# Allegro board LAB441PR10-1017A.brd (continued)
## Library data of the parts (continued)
PQ101 QE9 = MMST3904-7-F_SOT323-3
PQ102 PQ103 = 2N7002KDWH_SOT363-6
PQ201 = CSD87312Q3E_SON8-4
PQ202 = DCX124EK-7-F_SC74R-6
PQ203 = SIR472DP-T1-GE3_POWERPAK8-5
PQ204 = SI4835DDY-T1-E3_SO8
PQ205 = SI7716ADN-T1-GE3_POWERPAK8-5
PQ206 PQ500 = DMN65D8LW-7_SOT323-3
PQ300 PQ301 = CSD87330Q3D_SON8-7
PQ409 QA1 QA3 QE12 QH6 QH7 = DMN66D0LDW-7_SOT363-6
PQ600 = MDV1528URH_PDFN33-8-5
PQ601 = MDV1526URH_PDFN33-8-5
PR107 PR309 PR310 PR402 PR407 R541 R1332 R1393 = R_0805
PR109 PR207 PR221 PR502 PR602 PR717 R1240 = R_1206
PR202 PR219 = R_1206_4P-D
PR211 PR222 PR307 PR308 PR503 PR600 PR603 PR714 PR715 PR721 R307 R531 R1242 RA84 RH350 RH405 RH407 RH408 = R_0603
PR732 R1321 R1322 R1326 R1329-R1331 R1342 R1344 R2669 RH340 = R0805_0OHM
PRP100 RP2 RP4-RP8 RP14-RP16 RP20 RP21 RPE5 RPE7 = RP_0804_8P4R
PU200 = BQ24777RUYR_WQFN28_4X4
PU300 = TPS51285BRUKR_QFN20_3X3
PU400 PU401 = TLV62150RGTR_QFN16_3X3
PU404 = LM393DMR2G_MICRO8
PU405 PU406 = M74VHC1GT00DFT2G_SC70-5
PU500 = SY8206DQNC_QFN10_3X3
PU600 = G5616ARZ1U_TQFN20_3X3
PU700 = TPS51624RSM_QFN32_4X4
PU701 = CSD97374CQ4M_SON8_3P5X4P5
Q39 Q40 Q71 Q305 Q362 QA6 QA8 QA9 QC5 = SSM3K7002FU_SC70-3
Q70 = AO4407AL_SO8
Q360 = SIS412DN-T1-GE3_POWERPAK8-5
Q361 = SI1553CDL-T1-GE3_SC70-6
QA7 QV2 = LBSS138LT1G_SOT23-3
QE3 QE4 QE8 QE10 QE11 = MMBT3904WT1G_SC70-3
R309 R1125 R1318 R1320 R1323 R1343 R2670 R2671 RA80 RA83 RH341 RH348 RH354-RH357 RH3527 = R0603_0OHM
RP13 = RP_1206_10P8R
SW2 = SW_SKRBAAE010_4P
SW3 = SW_NTC311-EA1T-A160T_4P
SW4 = SW_SSAL120100_3P
T2 T123-T125 T226-T231 T263-T269 T273 T275-T279 T281 T282 T284 T286-T293 = TPC12
U34 = APE8937GN2_DFN8_2X2
U48 = W25Q64FVSSIQ_SO8
U652 = AT97SC3205_TSSOP28
U663 = 74CBTLV3126DS_SSOP16
U664 U715-U720 = TPS22966DPUR_SON14_2X3
U671 = TXB0104PWR_TSSOP14
U672 UC1 = 74AUP1G07GW_TSSOP5
U673 = NCP4545IMNTWG_QFN18_3X3
U675 U697 UH5 = MC74VHC1G08DFT2G_SC70-5
U679 = NLSX0102FCT1G_FLIP-CHIP8
U682 U683 = NL17SZ14DFT2G_SOT353-5
U699 = MC74VHC1G32DFT2G_SC70-5
U708 = SN74AUP1G04DCKR_SC70-5
U726 = AP2337SA-7_SOT23-3
U727 = W25Q32FVSSIQ_SO8
U728 = G9091-330TO1U_TSOT-23-5
UA2 = ALC3263-CG_QFN56_7X7
UC6 = TC7SH08FU_SSOP5
UCPU1 = SHARK-BAY-ULT_BGA_1168P-T
UD1 UD3 UD4 UD7 UD28 UD29 UD31 UD32 = MT41J256M16RE-15E-D_FBGA_96P
UE4 = MCP23017T-E-ML_QFN28_6X6
UE5 = MEC5085-LZY_DQFN132_11X11
US2 = G547I1P81U_MSOP8
UV1 = SN74CBT3257CPWR_TSSOP16
YE1 = Y_Q13FC135000040_2P
YH1 = Y_CM31532768DZFT_2P
YH2 = Y_X3G024000DC1H_4P

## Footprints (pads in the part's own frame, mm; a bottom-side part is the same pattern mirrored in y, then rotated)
2N7002KDWH_SOT363-6
  oval 0.356x0.889 smd: 1(0,0) 2(0.65,0) 3(1.3,0) 4(1.3,1.6) 5(0.65,1.6) 6(0,1.6)
74AUP1G07GW_TSSOP5
  oval 0.381x1.346 smd: 1(0,0) 2(0.65,0) 3(1.3,0) 4(1.3,1.79) 5(0,1.79)
74CBTLV3126DS_SSOP16
  oval 0.381x1.676 smd: 1(0,0) 2(0.635,0) 3(1.27,0) 4(1.905,0) 5(2.54,0) 6(3.175,0) 7(3.81,0) 8(4.445,0) 9(4.445,5.35) 10(3.81,5.35) 11(3.175,5.35) 12(2.54,5.35) 13(1.905,5.35) 14(1.27,5.35) 15(0.635,5.35) 16(0,5.35)
ACES_50224-00401-001_4P
  oval 0.61x1.549 smd: 1(0,0) 2(1,0) 3(2,0) 4(3,0)
  rect 1.194x1.803 smd: 5(4.3,-3.875) 6(-1.3,-3.875)
ACES_50278-00201-001_2P
  oval 0.787x1.905 smd: 1(0,0) 2(1.25,0)
  rect 1.295x3.353 smd: 3(-2.85,-4.925) 4(4.1,-4.925)
ACES_50398-04041-001_40P
  oval 0.254x1.295 smd: 1(0,0) 2(0.5,0) 3(1,0) 4(1.5,0) 5(2,0) 6(2.5,0) 7(3,0) 8(3.5,0) 9(4,0) 10(4.5,0) 11(5,0) 12(5.5,0) 13(6,0) 14(6.5,0) 15(7,0) 16(7.5,0) 17(8,0) 18(8.5,0) 19(9,0) 20(9.5,0) 21(10,0) 22(10.5,0) 23(11,0) 24(11.5,0) 25(12,0) 26(12.5,0) 27(13,0) 28(13.5,0) 29(14,0) 30(14.5,0) 31(15,0) 32(15.5,0) 33(16,0) 34(16.5,0) 35(17,0) 36(17.5,0) 37(18,0) 38(18.5,0) 39(19,0) 40(19.5,0)
  rect 1.194x3.2 smd: 41(-2.4,1.95) 45(21.9,1.95)
  rect 2.311x1.295 smd: 42(0.85,3.9) 43(9.75,3.9) 44(18.65,3.9)
ACES_50506-01841-P01_18P
  oval 0.305x0.889 smd: 1(0,0) 2(0.5,0) 3(1,0) 4(1.5,0) 5(2,0) 6(2.5,0) 7(3,0) 8(3.5,0) 9(4,0) 10(4.5,0) 11(5,0) 12(5.5,0) 13(6,0) 14(6.5,0) 15(7,0) 16(7.5,0) 17(8,0) 18(8.5,0)
  rect 0.991x2.007 smd: 19(-2.1,-3.05) 20(10.6,-3.05)
ACES_88266-05001_5P
  oval 0.787x2.007 smd: 1(0,0) 2(1.25,0) 3(2.5,0) 4(3.75,0) 5(5,0)
  rect 2.007x2.489 smd: 6(7.2,-4.05) 7(-2.2,-4.05)
ALC3263-CG_QFN56_7X7
  oval 0.203x0.889 smd: 1(0,0) 2(0.4,0) 3(0.8,0) 4(1.2,0) 5(1.6,0) 6(2,0) 7(2.4,0) 8(2.8,0) 9(3.2,0) 10(3.6,0) 11(4,0) 12(4.4,0) 13(4.8,0) 14(5.2,0) 29(5.2,7.1) 30(4.8,7.1) 31(4.4,7.1) 32(4,7.1) 33(3.6,7.1) 34(3.2,7.1) 35(2.8,7.1) 36(2.4,7.1) 37(2,7.1) 38(1.6,7.1) 39(1.2,7.1) 40(0.8,7.1) 41(0.4,7.1) 42(0,7.1)
  oval 0.889x0.203 smd: 15(6.15,0.95) 16(6.15,1.35) 17(6.15,1.75) 18(6.15,2.15) 19(6.15,2.55) 20(6.15,2.95) 21(6.15,3.35) 22(6.15,3.75) 23(6.15,4.15) 24(6.15,4.55) 25(6.15,4.95) 26(6.15,5.35) 27(6.15,5.75) 28(6.15,6.15) 43(-0.95,6.15) 44(-0.95,5.75) 45(-0.95,5.35) 46(-0.95,4.95) 47(-0.95,4.55) 48(-0.95,4.15) 49(-0.95,3.75) 50(-0.95,3.35) 51(-0.95,2.95) 52(-0.95,2.55) 53(-0.95,2.15) 54(-0.95,1.75) 55(-0.95,1.35) 56(-0.95,0.95)
  rect 4.597x4.597 smd: 57(2.6,3.55)
AO4407AL_SO8
  oval 0.635x1.854 smd: 1(0,0) 2(1.27,0) 3(2.54,0) 4(3.81,0) 5(3.81,5.165) 6(2.54,5.165) 7(1.27,5.165) 8(0,5.165)
AP2337SA-7_SOT23-3
  oval 1.016x1.524 smd: 1(0,0) 2(0.965,2.083) 3(-0.965,2.083)
APE8937GN2_DFN8_2X2
  oval 0.254x0.787 smd: 1(0,0) 2(0.5,0) 3(1,0) 4(1.5,0) 5(1.5,2.2) 6(1,2.2) 7(0.5,2.2) 8(0,2.2)
  rect 1.6x0.889 smd: 9(0.75,1.1)
AT97SC3205_TSSOP28
  oval 0.381x1.626 smd: 1(0,0) 2(0.65,0) 3(1.3,0) 4(1.95,0) 5(2.6,0) 6(3.25,0) 7(3.9,0) 8(4.55,0) 9(5.2,0) 10(5.85,0) 11(6.5,0) 12(7.15,0) 13(7.8,0) 14(8.45,0) 15(8.45,5.8) 16(7.8,5.8) 17(7.15,5.8) 18(6.5,5.8) 19(5.85,5.8) 20(5.2,5.8) 21(4.55,5.8) 22(3.9,5.8) 23(3.25,5.8) 24(2.6,5.8) 25(1.95,5.8) 26(1.3,5.8) 27(0.65,5.8) 28(0,5.8)
AZ5125-01HPR7G_SOD523-2
  rect 0.61x0.787 smd: 1(0,0) 2(1.5,0)
AZ5125-02SPR7G_SOT23-3
  oval 1.016x1.524 smd: 1(0,0) 2(0.965,2.083) 3(-0.965,2.083)
BAS40-04_SOT23-3
  oval 1.016x1.524 smd: 1(0,0) 2(0.965,2.083) 3(-0.965,2.083)
BAT54A-7-F_SOT23-3
  oval 1.016x1.524 smd: 1(0,0) 2(0.965,2.083) 3(-0.965,2.083)
BAT54CW-7-F_SOT323-3
  oval 0.711x0.889 smd: 1(0,0) 2(-0.65,-1.9) 3(0.65,-1.9)
BQ24777RUYR_WQFN28_4X4
  oval 0.889x0.203 smd: 1(0,0) 2(0,-0.4) 3(0,-0.8) 4(0,-1.2) 5(0,-1.6) 6(0,-2) 7(0,-2.4) 15(4.1,-2.4) 16(4.1,-2) 17(4.1,-1.6) 18(4.1,-1.2) 19(4.1,-0.8) 20(4.1,-0.4) 21(4.1,0)
  oval 0.203x0.889 smd: 8(0.85,-3.25) 9(1.25,-3.25) 10(1.65,-3.25) 11(2.05,-3.25) 12(2.45,-3.25) 13(2.85,-3.25) 14(3.25,-3.25) 22(3.25,0.85) 23(2.85,0.85) 24(2.45,0.85) 25(2.05,0.85) 26(1.65,0.85) 27(1.25,0.85) 28(0.85,0.85)
  rect 2.591x2.591 smd: 29(2.05,-1.2)
C_0402
  rect 0.508x0.559 smd: 1(0,0) 2(0.914,0)
C_0603
  rect 0.635x0.889 smd: 1(0,0) 2(1.397,0)
C_0805
  rect 0.813x1.397 smd: 1(0,0) 2(1.702,0)
C_1210
  oval 1.27x2.794 smd: 1(0,0) 2(3.048,0)
C_A1
  rect 1.346x1.499 smd: 1(0,0) 2(2.45,0)
C_B
  rect 1.549x2.464 smd: 1(0,0) 2(3.378,0)
C_B2
  rect 1.346x2.692 smd: 1(0,0) 2(-2.75,0)
C_D2
  rect 2.388x2.794 smd: 1(0,0) 2(6.4,0)
CHILI_PBY100505T-600Y-N_2P
  rect 0.457x0.508 smd: 1(0,0) 2(0.85,0)
CONCR_213EBAA2FKA_67P
  round 1.092 hole 1.092 unplated: (-0.75,-5.275)
  round 1.6 hole 1.6 unplated: (19.25,-5.275)
  oval 0.305x1.549 smd: 1(0,0) 2(0.25,-7.55) 3(0.5,0) 4(0.75,-7.55) 5(1,0) 6(1.25,-7.55) 7(1.5,0) 8(1.75,-7.55) 9(2,0) 10(2.25,-7.55) 11(2.5,0) 12(2.75,-7.55) 13(3,0) 14(3.25,-7.55) 15(3.5,0) 16(3.75,-7.55) 17(4,0) 18(4.25,-7.55) 19(4.5,0) 20(4.75,-7.55) 21(5,0) 22(5.25,-7.55) 23(5.5,0) 24(7.75,-7.55) 25(8,0) 26(8.25,-7.55) 27(8.5,0) 28(8.75,-7.55) 29(9,0) 30(9.25,-7.55) 31(9.5,0) 32(9.75,-7.55) 33(10,0) 34(10.25,-7.55) 35(10.5,0) 36(10.75,-7.55) 37(11,0) 38(11.25,-7.55) 39(11.5,0) 40(11.75,-7.55) 41(12,0) 42(12.25,-7.55) 43(12.5,0) 44(12.75,-7.55) 45(13,0) 46(13.25,-7.55) 47(13.5,0) 48(13.75,-7.55) 49(14,0) 50(14.25,-7.55) 51(14.5,0) 52(14.75,-7.55) 53(15,0) 54(15.25,-7.55) 55(15.5,0) 56(15.75,-7.55) 57(16,0) 58(16.25,-7.55) 59(16.5,0) 60(16.75,-7.55) 61(17,0) 62(17.25,-7.55) 63(17.5,0) 64(17.75,-7.55) 65(18,0) 66(18.25,-7.55) 67(18.5,0)
  rect 1.194x2.743 smd: 68(-1.1,-0.775) 69(19.6,-0.775)
CONCR_213MAAA32FA_67P-T
  round 1.092 hole 1.092 unplated: (-0.75,-5.275)
  round 1.6 hole 1.6 unplated: (19.25,-5.275)
  oval 0.305x1.549 smd: 1(0,0) 2(0.25,-7.55) 3(0.5,0) 4(0.75,-7.55) 5(1,0) 6(1.25,-7.55) 7(1.5,0) 8(1.75,-7.55) 9(2,0) 10(2.25,-7.55) 11(2.5,0) 12(2.75,-7.55) 13(3,0) 14(3.25,-7.55) 15(3.5,0) 16(3.75,-7.55) 17(4,0) 18(4.25,-7.55) 19(4.5,0) 20(4.75,-7.55) 21(5,0) 22(5.25,-7.55) 23(5.5,0) 24(5.75,-7.55) 25(6,0) 26(6.25,-7.55) 27(6.5,0) 28(6.75,-7.55) 29(7,0) 30(7.25,-7.55) 31(7.5,0) 32(7.75,-7.55) 33(8,0) 34(8.25,-7.55) 35(8.5,0) 36(8.75,-7.55) 37(9,0) 38(9.25,-7.55) 39(9.5,0) 40(9.75,-7.55) 41(10,0) 42(10.25,-7.55) 43(10.5,0) 44(10.75,-7.55) 45(11,0) 46(11.25,-7.55) 47(11.5,0) 48(11.75,-7.55) 49(12,0) 50(12.25,-7.55) 51(12.5,0) 52(12.75,-7.55) 53(13,0) 54(13.25,-7.55) 55(13.5,0) 56(13.75,-7.55) 57(14,0) 58(14.25,-7.55) 59(16.5,0) 60(16.75,-7.55) 61(17,0) 62(17.25,-7.55) 63(17.5,0) 64(17.75,-7.55) 65(18,0) 66(18.25,-7.55) 67(18.5,0)
  rect 1.194x2.743 smd: 68(-1.1,-0.775) 69(19.6,-0.775)
CSD87312Q3E_SON8-4
  rect 2.388x0.66 smd: 1(0,0)
  rect 0.432x0.66 smd: 2(0.975,2.95)
  rect 1.753x0.66 smd: 3(-0.325,2.95)
  custom 0.475x0.475 smd: 4(0,1.475)
CSD87330Q3D_SON8-7
  oval 1.092x0.66 smd: 1(0,0)
  oval 0.432x0.66 smd: 2(0.975,0) 3(1.625,0) 4(1.625,2.95) 5(0.975,2.95) 6(0.325,2.95) 7(-0.325,2.95)
  custom 0.475x0.475 smd: 8(0.65,1.475)
CSD97374CQ4M_SON8_3P5X4P5
  oval 0.203x0.889 smd: 1(0,0) 2(0.4,0) 3(0.8,0) 6(0.8,3.5) 7(0.4,3.5) 8(0,3.5)
  custom 0.225x0.225 smd: 4(2.2,0.262) 5(2.2,3.238)
  rect 4.039x2.21 smd: 9(1.6,1.75)
CVILU_CI1806M2HRP-NH_6P
  oval 0.508x0.991 smd: 1(0,0) 2(0.8,0) 3(1.6,0) 4(2.4,0) 5(3.2,0) 6(4,0)
  rect 1.194x1.702 smd: 7(5.3,-1.95) 8(-1.3,-1.95)
DCX124EK-7-F_SC74R-6
  oval 0.559x0.787 smd: 1(0,0) 2(-0.95,0) 3(-1.9,0) 4(-1.9,2.4) 5(-0.95,2.4) 6(0,2.4)
DMN65D8LW-7_SOT323-3
  oval 0.711x0.889 smd: 1(0,0) 2(-0.65,-1.9) 3(0.65,-1.9)
DMN66D0LDW-7_SOT363-6
  oval 0.432x0.61 smd: 1(0,0) 2(0.65,0) 3(1.3,0) 4(1.3,1.9) 5(0.65,1.9) 6(0,1.9)
E-T_6705K-Y08N-40L_8P
  oval 0.305x1.092 smd: 1(0,0) 2(0.5,0) 3(1,0) 4(1.5,0) 5(2,0) 6(2.5,0) 7(3,0) 8(3.5,0)
  rect 0.991x2.007 smd: 9(-2.1,-3.15) 10(5.6,-3.15)
E-T_6705K-Y15N-00L_15P
  oval 0.305x0.889 smd: 1(0,0) 2(0.5,0) 3(1,0) 4(1.5,0) 5(2,0) 6(2.5,0) 7(3,0) 8(3.5,0) 9(4,0) 10(4.5,0) 11(5,0) 12(5.5,0) 13(6,0) 14(6.5,0) 15(7,0)
  rect 0.991x2.007 smd: 16(-2.1,-3.05) 17(9.1,-3.05)
E-T_6710K-Y15M-31L_15P
  oval 0.305x0.965 smd: 1(0,0) 2(0.5,0) 3(1,0) 4(1.5,0) 5(2,0) 6(2.5,0) 7(3,0) 8(3.5,0) 9(4,0) 10(4.5,0) 11(5,0) 12(5.5,0) 13(6,0) 14(6.5,0) 15(7,0)
  rect 0.305x1.143 smd: 16(7.885,-2.965) 17(-0.885,-2.965)
EMIST_SUL-12A2M_1P
  rect 6.909x1.194 smd: 1(0,0)
ESD207-B1-02EL_TSLP-2-19-2
  rect 0.356x0.61 smd: 1(0,0) 2(0.65,0)
FDV301N_NL_SOT23-3
  oval 1.016x1.524 smd: 1(0,0) 2(0.965,2.083) 3(-0.965,2.083)
FIDUCIAL_C40M80
  round 1.016 smd: 1(0,0)
FOX_GS73091-10272-7H_9P-T
  rect 0.66x5.004 smd: 1(0,0) 2(-1.5,0) 3(-3,0) 4(-4.5,0) 5(-6,0) 6(-7.5,0) 7(-9,0) 8(-10.5,0) 9(-12,0)
  rect 2.489x2.997 smd: 10(-14.5,4.45) 11(2.5,4.45)
G547I1P81U_MSOP8
  oval 0.381x1.549 smd: 1(0,0) 2(0.65,0) 3(1.3,0) 4(1.95,0) 5(1.95,4.37) 6(1.3,4.37) 7(0.65,4.37) 8(0,4.37)
G5616ARZ1U_TQFN20_3X3
  oval 0.203x1.016 smd: 1(0,0) 2(0.4,0) 3(0.8,0) 4(1.2,0) 5(1.6,0) 11(1.6,2.975) 12(1.2,2.975) 13(0.8,2.975) 14(0.4,2.975) 15(0,2.975)
  oval 1.016x0.203 smd: 6(2.288,0.688) 7(2.288,1.088) 8(2.288,1.488) 9(2.288,1.888) 10(2.288,2.288) 16(-0.688,2.288) 17(-0.688,1.888) 18(-0.688,1.488) 19(-0.688,1.088) 20(-0.688,0.688)
  rect 1.6x1.6 smd: 21(0.8,1.488)
G9091-330TO1U_TSOT-23-5
  oval 0.508x0.965 smd: 1(0,0) 2(0.95,0) 3(1.9,0) 4(1.9,2.35) 5(0,2.35)
H_1P8N
  round 1.803 hole 1.803 unplated: (0,0)
H_2P0
  round 2.515 hole 2.007: 1(0,0)
H_2P3X1P8N
  oval 2.311x1.803 hole 2.311x1.803 unplated: (0,0)
H_3P2X0P8
  oval 3.708x1.295 hole 3.2x0.787: 1(0,0)
H_3P3
  round 3.81 hole 3.302: 1(0,0)
HB_A531015-SCHR21_10P
  oval 0.305x0.889 smd: 1(0,0) 2(0.5,0) 3(1,0) 4(1.5,0) 5(2,0) 6(2.5,0) 7(3,0) 8(3.5,0) 9(4,0) 10(4.5,0)
  rect 0.991x2.007 smd: 11(6.6,-3.05) 12(-2.1,-3.05)
INPAQ_HCM1012GH900BP_4P
  rect 0.711x0.305 smd: 1(0,0) 2(1.25,0) 3(1.25,-0.5) 4(0,-0.5)
IP4292CZ10-TBR_XSON10_2P5X1
  oval 0.254x0.889 smd: 1(0,0)
  oval 0.254x0.838 smd: 2(0.5,-0.025) 3(1,-0.025) 4(1.5,-0.025) 5(2,-0.025) 6(2,1.125) 7(1.5,1.125) 8(1,1.125) 9(0.5,1.125) 10(0,1.125)
JUMP_43X39
  custom 0.191x0.191 smd: 1(0,0) 2(0.914,0)
JUMP_43X118
  custom 0.187x0.187 smd: 1(0,0) 2(1.1,0)
JXT_FP270H-061G1AM_61P
  oval 0.305x0.787 smd: 1(0,0) 3(0.6,0) 5(1.2,0) 7(1.8,0) 9(2.4,0) 11(3,0) 13(3.6,0) 15(4.2,0) 17(4.8,0) 19(5.4,0) 21(6,0) 23(6.6,0) 25(7.2,0) 27(7.8,0) 29(8.4,0) 31(9,0) 33(9.6,0) 35(10.2,0) 37(10.8,0) 39(11.4,0) 41(12,0) 43(12.6,0) 45(13.2,0) 47(13.8,0) 49(14.4,0) 51(15,0) 53(15.6,0) 55(16.2,0) 57(16.8,0) 59(17.4,0) 61(18,0)
  oval 0.305x0.66 smd: 2(0.3,2.875) 4(0.9,2.875) 6(1.5,2.875) 8(2.1,2.875) 10(2.7,2.875) 12(3.3,2.875) 14(3.9,2.875) 16(4.5,2.875) 18(5.1,2.875) 20(5.7,2.875) 22(6.3,2.875) 24(6.9,2.875) 26(7.5,2.875) 28(8.1,2.875) 30(8.7,2.875) 32(9.3,2.875) 34(9.9,2.875) 36(10.5,2.875) 38(11.1,2.875) 40(11.7,2.875) 42(12.3,2.875) 44(12.9,2.875) 46(13.5,2.875) 48(14.1,2.875) 50(14.7,2.875) 52(15.3,2.875) 54(15.9,2.875) 56(16.5,2.875) 58(17.1,2.875) 60(17.7,2.875)
  rect 0.305x1.143 smd: 62(-0.65,0.375) 63(18.65,0.375)
L30ESDL5V0C3-2_SOT23-3
  oval 1.016x1.524 smd: 1(0,0) 2(0.965,2.083) 3(-0.965,2.083)
L_7X7X3_M_2P
  rect 2.362x3.505 smd: 1(0,0) 2(6.05,0)
LBSS138LT1G_SOT23-3
  oval 1.016x1.524 smd: 1(0,0) 2(0.965,2.083) 3(-0.965,2.083)
LED_27-11-T1D-CP1Q1RY-3C_2P
  rect 0.991x0.991 smd: 1(0,0) 2(1.9,0)
LM393DMR2G_MICRO8
  oval 0.381x1.041 smd: 1(0,0) 2(0.65,0) 3(1.3,0) 4(1.95,0) 5(1.95,4.24) 6(1.3,4.24) 7(0.65,4.24) 8(0,4.24)
M74VHC1GT00DFT2G_SC70-5
  oval 0.406x0.508 smd: 1(0,0) 2(0.65,0) 3(1.3,0) 4(1.3,1.9) 5(0,1.9)
MAG_MMD06CZER15MG_4P
  custom 0.686x0.686 smd: 1(0,0) 4(8.509,0)
  rect 2.362x0.508 smd: 2(1.448,0) 3(7.061,0)
MC74VHC1G08DFT2G_SC70-5
  oval 0.381x0.711 smd: 1(0,0) 2(0.65,0) 3(1.3,0) 4(1.3,1.9) 5(0,1.9)
MC74VHC1G32DFT2G_SC70-5
  oval 0.457x0.711 smd: 1(-0.65,-0.925) 2(0,-0.925) 3(0.65,-0.925) 4(0.65,0.925) 5(-0.65,0.925)
MCP23017T-E-ML_QFN28_6X6
  oval 0.457x1.041 smd: 1(0,0) 2(0.65,0) 3(1.3,0) 4(1.95,0) 5(2.6,0) 6(3.25,0) 7(3.9,0) 15(3.9,5.95) 16(3.25,5.95) 17(2.6,5.95) 18(1.95,5.95) 19(1.3,5.95) 20(0.65,5.95) 21(0,5.95)
  oval 1.041x0.457 smd: 8(4.925,1.025) 9(4.925,1.675) 10(4.925,2.325) 11(4.925,2.975) 12(4.925,3.625) 13(4.925,4.275) 14(4.925,4.925) 22(-1.025,4.925) 23(-1.025,4.275) 24(-1.025,3.625) 25(-1.025,2.975) 26(-1.025,2.325) 27(-1.025,1.675) 28(-1.025,1.025)
  rect 3.708x3.708 smd: 29(1.95,2.975)
MDV1526URH_PDFN33-8-5
  oval 0.406x0.991 smd: 1(0,0) 2(0.66,0) 3(1.32,0) 4(1.98,0)
  custom 0.559x0.559 smd: 5(0.99,2.248)
MDV1528URH_PDFN33-8-5
  oval 0.406x0.61 smd: 1(0,0) 2(0.65,0) 3(1.3,0) 4(1.95,0)
  custom 0.65x0.65 smd: 5(0.975,1.475)
MEC5085-LZY_DQFN132_11X11
  oval 0.279x0.711 smd: A1(0,0) A2(0.5,0) A3(1,0) A4(1.5,0) A5(2,0) A6(2.5,0) A7(3,0) A8(3.5,0) A9(4,0) A10(4.5,0) A11(5,0) A12(5.5,0) A13(6,0) A14(6.5,0) A15(7,0) A16(7.5,0) A33(7.5,10.9) A34(7,10.9) A35(6.5,10.9) A36(6,10.9) A37(5.5,10.9) A38(5,10.9) A39(4.5,10.9) A40(4,10.9) A41(3.5,10.9) A42(3,10.9) A43(2.5,10.9) A44(2,10.9) A45(1.5,10.9) A46(1,10.9) A47(0.5,10.9) A48(0,10.9)
  oval 0.711x0.279 smd: A17(9.2,1.7) A18(9.2,2.2) A19(9.2,2.7) A20(9.2,3.2) A21(9.2,3.7) A22(9.2,4.2) A23(9.2,4.7) A24(9.2,5.2) A25(9.2,5.7) A26(9.2,6.2) A27(9.2,6.7) A28(9.2,7.2) A29(9.2,7.7) A30(9.2,8.2) A31(9.2,8.7) A32(9.2,9.2) A49(-1.7,9.2) A50(-1.7,8.7) A51(-1.7,8.2) A52(-1.7,7.7) A53(-1.7,7.2) A54(-1.7,6.7) A55(-1.7,6.2) A56(-1.7,5.7) A57(-1.7,5.2) A58(-1.7,4.7) A59(-1.7,4.2) A60(-1.7,3.7) A61(-1.7,3.2) A62(-1.7,2.7) A63(-1.7,2.2) A64(-1.7,1.7)
  oval 0.305x0.61 smd: B1(-0.25,0.85) B2(0.25,0.85) B3(0.75,0.85) B4(1.25,0.85) B5(1.75,0.85) B6(2.25,0.85) B7(2.75,0.85) B8(3.25,0.85) B9(3.75,0.85) B10(4.25,0.85) B11(4.75,0.85) B12(5.25,0.85) B13(5.75,0.85) B14(6.25,0.85) B15(6.75,0.85) B16(7.25,0.85) B17(7.75,0.85) B35(7.75,10.05) B36(7.25,10.05) B37(6.75,10.05) B38(6.25,10.05) B39(5.75,10.05) B40(5.25,10.05) B41(4.75,10.05) B42(4.25,10.05) B43(3.75,10.05) B44(3.25,10.05) B45(2.75,10.05) B46(2.25,10.05) B47(1.75,10.05) B48(1.25,10.05) B49(0.75,10.05) B50(0.25,10.05) B51(-0.25,10.05)
  oval 0.61x0.305 smd: B18(8.35,1.45) B19(8.35,1.95) B20(8.35,2.45) B21(8.35,2.95) B22(8.35,3.45) B23(8.35,3.95) B24(8.35,4.45) B25(8.35,4.95) B26(8.35,5.45) B27(8.35,5.95) B28(8.35,6.45) B29(8.35,6.95) B30(8.35,7.45) B31(8.35,7.95) B32(8.35,8.45) B33(8.35,8.95) B34(8.35,9.45) B52(-0.85,9.45) B53(-0.85,8.95) B54(-0.85,8.45) B55(-0.85,7.95) B56(-0.85,7.45) B57(-0.85,6.95) B58(-0.85,6.45) B59(-0.85,5.95) B60(-0.85,5.45) B61(-0.85,4.95) B62(-0.85,4.45) B63(-0.85,3.95) B64(-0.85,3.45) B65(-0.85,2.95) B66(-0.85,2.45) B67(-0.85,1.95) B68(-0.85,1.45)
  rect 5.004x5.004 smd: C1(3.75,5.45)
MMBT3904WT1G_SC70-3
  oval 0.711x0.889 smd: 1(0,0) 2(0.65,1.9) 3(-0.65,1.9)
MMST3904-7-F_SOT323-3
  oval 0.711x0.889 smd: 1(0,0) 2(0.65,1.9) 3(-0.65,1.9)
MT41J256M16RE-15E-D_FBGA_96P
  round 0.343 smd: A1(0,0) A2(0.8,0) A3(1.6,0) A7(4.8,0) A8(5.6,0) A9(6.4,0) B1(0,-0.8) B2(0.8,-0.8) B3(1.6,-0.8) B7(4.8,-0.8) B8(5.6,-0.8) B9(6.4,-0.8) C1(0,-1.6) C2(0.8,-1.6) C3(1.6,-1.6) C7(4.8,-1.6) C8(5.6,-1.6) C9(6.4,-1.6) D1(0,-2.4) D2(0.8,-2.4) D3(1.6,-2.4) D7(4.8,-2.4) D8(5.6,-2.4) D9(6.4,-2.4) E1(0,-3.2) E2(0.8,-3.2) E3(1.6,-3.2) E7(4.8,-3.2) E8(5.6,-3.2) E9(6.4,-3.2) F1(0,-4) F2(0.8,-4) F3(1.6,-4) F7(4.8,-4) F8(5.6,-4) F9(6.4,-4) G1(0,-4.8) G2(0.8,-4.8) G3(1.6,-4.8) G7(4.8,-4.8) G8(5.6,-4.8) G9(6.4,-4.8) H1(0,-5.6) H2(0.8,-5.6) H3(1.6,-5.6) H7(4.8,-5.6) H8(5.6,-5.6) H9(6.4,-5.6) J1(0,-6.4) J2(0.8,-6.4) J3(1.6,-6.4) J7(4.8,-6.4) J8(5.6,-6.4) J9(6.4,-6.4) K1(0,-7.2) K2(0.8,-7.2) K3(1.6,-7.2) K7(4.8,-7.2) K8(5.6,-7.2) K9(6.4,-7.2) L1(0,-8) L2(0.8,-8) L3(1.6,-8) L7(4.8,-8) L8(5.6,-8) L9(6.4,-8) M1(0,-8.8) M2(0.8,-8.8) M3(1.6,-8.8) M7(4.8,-8.8) M8(5.6,-8.8) M9(6.4,-8.8) N1(0,-9.6) N2(0.8,-9.6) N3(1.6,-9.6) N7(4.8,-9.6) N8(5.6,-9.6) N9(6.4,-9.6) P1(0,-10.4) P2(0.8,-10.4) P3(1.6,-10.4) P7(4.8,-10.4) P8(5.6,-10.4) P9(6.4,-10.4) R1(0,-11.2) R2(0.8,-11.2) R3(1.6,-11.2) R7(4.8,-11.2) R8(5.6,-11.2) R9(6.4,-11.2) T1(0,-12) T2(0.8,-12) T3(1.6,-12) T7(4.8,-12) T8(5.6,-12) T9(6.4,-12)
MURAT_BLM15AG102SN1D_2P
  rect 0.457x0.508 smd: 1(0,0) 2(0.85,0)
MURAT_BLM15BB220SN1D_2P
  rect 0.508x0.762 smd: 1(0,0) 2(0.75,0)
MURAT_BLM15PX181SN1D_2P
  rect 0.508x0.762 smd: 1(0,0) 2(0.75,0)
MURAT_BLM15PX600SN1D_2P
  rect 0.457x0.508 smd: 1(0,0) 2(0.85,0)
MURAT_BLM21PG600SN1D_L0805_2P
  rect 0.991x1.753 smd: 1(0,0) 2(1.5,0)
MURAT_DLW21HN900HQ2L_4P
  rect 0.889x0.356 smd: 1(0,0) 2(1.7,0) 3(1.7,0.85) 4(0,0.85)
MURAT_DLW21SN670HQ2L_4P
  rect 0.889x0.406 smd: 1(0,0) 2(1.7,0) 3(1.7,0.8) 4(0,0.8)
MURAT_LQM2MPN2R2NG0L_2P
  rect 0.787x1.803 smd: 1(0,0) 2(1.6,0)
NCP4545IMNTWG_QFN18_3X3
  oval 0.254x0.94 smd: 1(0,0) 2(0.5,0) 3(1,0) 4(1.5,0) 10(1.5,3.05) 11(1,3.05) 12(0.5,3.05) 13(0,3.05)
  oval 0.94x0.254 smd: 5(2.275,0.525) 6(2.275,1.025) 7(2.275,1.525) 8(2.275,2.025) 9(2.275,2.525) 14(-0.775,2.525) 15(-0.775,2.025) 16(-0.775,1.525) 17(-0.775,1.025) 18(-0.775,0.525)
  rect 1.854x1.854 smd: 19(0.75,1.525)
NL17SZ14DFT2G_SOT353-5
  oval 0.381x1.219 smd: 1(0,0) 2(0.65,0) 3(1.3,0) 4(1.3,1.9) 5(0,1.9)
NLSX0102FCT1G_FLIP-CHIP8
  round 0.254 smd: A1(0,0) A2(0.5,0) B1(0,-0.5) B2(0.5,-0.5) C1(0,-1) C2(0.5,-1) D1(0,-1.5) D2(0.5,-1.5)
PESD5V0U2BT_SOT23-3
  oval 1.016x1.524 smd: 1(0,0) 2(0.965,2.083) 3(-0.965,2.083)
PJDLC05C_SOT23-3
  oval 1.016x1.524 smd: 1(0,0) 2(0.965,2.083) 3(-0.965,2.083)
R0402_0OHM
  rect 0.508x0.559 smd: 1(0,0) 2(0.914,0)
R0603_0OHM
  rect 0.635x0.889 smd: 1(0,0) 2(1.397,0)
R0805_0OHM
  rect 0.813x1.397 smd: 1(0,0) 2(1.702,0)
R_0402
  rect 0.508x0.559 smd: 1(0,0) 2(0.914,0)
R_0603
  rect 0.635x0.889 smd: 1(0,0) 2(1.397,0)
R_0805
  rect 0.813x1.397 smd: 1(0,0) 2(1.702,0)
R_1206
  rect 1.016x1.651 smd: 1(0,0) 2(2.667,0)
R_1206_4P-D
  custom 0.445x0.445 smd: 1(0,0) 4(5.004,0)
  custom 0.114x0.114 smd: 2(1.194,0) 3(3.81,0)
RB751S40T1G_SOD523-2
  rect 0.406x0.406 smd: 1(0,0) 2(1.4,0)
RP_0804_8P4R
  oval 0.66x0.254 smd: 1(0,0) 2(0,-0.5) 3(0,-1) 4(0,-1.5) 5(1.15,-1.5) 6(1.15,-1) 7(1.15,-0.5) 8(1.15,0)
RP_1206_10P8R
  oval 0.356x0.914 smd: 1(0,0) 2(0.65,0) 3(1.3,0) 4(1.95,0) 5(2.6,0) 6(2.6,1.422) 7(1.95,1.422) 8(1.3,1.422) 9(0.65,1.422) 10(0,1.422)
SAMTE_BSH-030-01-L-D-A_60P
  round 1.016 hole 1.016 unplated: (-2.81,5.53) (17.316,5.53)
  oval 0.279x2.261 smd: 1(0,0) 2(0,5.728) 3(0.5,0) 4(0.5,5.728) 5(1,0) 6(1,5.728) 7(1.5,0) 8(1.5,5.728) 9(2,0) 10(2,5.728) 11(2.5,0) 12(2.5,5.728) 13(3,0) 14(3,5.728) 15(3.5,0) 16(3.5,5.728) 17(4,0) 18(4,5.728) 19(4.5,0) 20(4.5,5.728) 21(5,0) 22(5,5.728) 23(5.5,0) 24(5.5,5.728) 25(6,0) 26(6,5.728) 27(6.5,0) 28(6.5,5.728) 29(7,0) 30(7,5.728) 31(7.5,0) 32(7.5,5.728) 33(8,0) 34(8,5.728) 35(8.5,0) 36(8.5,5.728) 37(9,0) 38(9,5.728) 39(9.5,0) 40(9.5,5.728) 41(10,0) 42(10,5.728) 43(10.5,0) 44(10.5,5.728) 45(11,0) 46(11,5.728) 47(11.5,0) 48(11.5,5.728) 49(12,0) 50(12,5.728) 51(12.5,0) 52(12.5,5.728) 53(13,0) 54(13,5.728) 55(13.5,0) 56(13.5,5.728) 57(14,0) 58(14,5.728) 59(14.5,0) 60(14.5,5.728)
SDMK0340L-7-F_SOD323-2
  rect 1.346x0.66 smd: 1(0,0) 2(2.4,0)
SHARK-BAY-ULT_BGA_1168P-T
  round 0.508 smd: A3(-1.138,0) A62(-38.036,0) AW1(0,22.042) AW63(-38.628,22.057) AY2(-0.544,22.629) AY62(-38.062,22.629) B2(-0.508,0.508) B63(-38.628,0.592) C1(0,1.138)
  round 0.381 smd: A4(-1.895,0) A5(-2.555,0) A6(-3.749,0) A59(-35.9,0) A60(-36.726,0) A61(-37.386,0) AA9(-5.032,11.577) AA21(-11.687,11.488) AA23(-13.114,11.488) AA58(-35.377,11.328) AB10(-5.476,12.052) AB20(-11.179,11.895) AB21(-11.687,12.301) AB22(-12.606,11.895) AB23(-13.114,12.301) AB57(-35.057,11.979) AC9(-5.032,12.53) AC20(-11.179,12.708) AC22(-12.606,12.708) AC58(-35.377,12.629) AD10(-5.476,13.005) AD21(-11.687,13.114) AD23(-13.114,13.114) AD57(-35.057,13.279) AE9(-5.032,13.482) AE10(-5.476,13.957) AE20(-11.179,13.52) AE21(-11.687,13.927) AE22(-12.606,13.52) AE23(-13.114,13.927) AE58(-35.377,13.929) AF9(-5.032,14.435) AF11(-6.058,14.282) AF12(-6.871,14.282) AF14(-7.684,14.282) AF15(-8.496,14.282) AF17(-9.309,14.282) AF18(-10.122,14.282) AF20(-10.935,14.282) AF22(-12.606,14.333) AG10(-5.652,14.79) AG11(-6.464,14.79) AG13(-7.277,14.79) AG14(-8.09,14.79) AG16(-8.903,14.79) AG17(-9.716,14.79) AG19(-10.528,14.79) AG20(-11.341,14.79) AG23(-13.114,14.74) AG57(-35.057,14.58) AG58(-35.692,15.009) AH22(-12.606,15.146) AH24(-13.919,15.288) AH26(-15.22,15.288) AH28(-16.52,15.288) AH30(-17.821,15.288) AH32(-19.121,15.288) AH34(-20.422,15.288) AH36(-21.722,15.288) AH38(-23.023,15.288) AH40(-24.323,15.288) AH42(-25.624,15.288) AH44(-26.924,15.288) AH46(-28.224,15.288) AH49(-29.525,15.288) AH51(-30.825,15.288) AH53(-32.126,15.288) AH55(-33.426,15.288) AH57(-34.727,15.288) AJ23(-13.114,15.552) AJ25(-14.569,15.613) AJ27(-15.87,15.613) AJ29(-17.17,15.613) AJ31(-18.471,15.613) AJ33(-19.771,15.613) AJ35(-21.072,15.613) AJ37(-22.372,15.613) AJ39(-23.673,15.613) AJ41(-24.973,15.613) AJ43(-26.274,15.613) AJ45(-27.574,15.613) AJ47(-28.875,15.613) AJ50(-30.175,15.613) AJ52(-31.476,15.613) AJ54(-32.776,15.613) AJ56(-34.077,15.613) AJ58(-35.377,15.613) AT1(0,19.997) AT63(-38.628,19.848) AU1(0,20.658) AU63(-38.628,20.673) AV1(0,21.318) AV2(-0.66,21.308) AV62(-37.978,21.318) AV63(-38.628,21.333) AW2(-0.66,21.968) AW3(-1.321,21.968) AW61(-37.328,21.979) AW62(-37.978,21.979) AY3(-1.267,22.629) AY4(-1.928,22.629) AY5(-2.588,22.629) AY59(-36.088,22.629) AY60(-36.749,22.629) AY61(-37.409,22.629) B3(-1.26,0.65) B61(-37.315,0.66) B62(-37.978,0.724) C2(-0.65,1.26) C62(-37.978,1.384) C63(-38.628,1.316) D1(0,1.862) D63(-38.628,1.976) E1(0,2.522) E23(-13.332,2.601) E25(-14.714,2.601) E27(-15.839,2.601) E29(-17.221,2.601) E31(-18.349,2.601) E33(-19.728,2.601) E35(-20.856,2.601) E37(-22.235,2.601) E39(-23.363,2.601) E41(-24.745,2.601) E43(-25.87,2.601) E45(-27.252,2.601) E47(-28.377,2.601) E49(-29.759,2.601) E51(-30.886,2.601) E53(-32.266,2.601) E55(-33.393,2.601) E57(-34.773,2.601) E63(-38.628,2.647) F1(0,3.437) F22(-12.718,3.058) F24(-14.023,3.127) F26(-15.278,3.127) F28(-16.53,3.127) F30(-17.785,3.127) F32(-19.037,3.127) F34(-20.292,3.127) F36(-21.547,3.127) F38(-22.799,3.127) F40(-24.054,3.127) F42(-25.306,3.127) F44(-26.561,3.127) F46(-27.816,3.127) F48(-29.068,3.127) F50(-30.323,3.127) F52(-31.575,3.127) F54(-32.83,3.127) F56(-34.084,3.127) F58(-35.377,3.127) G22(-12.606,3.767) G23(-13.332,3.452) G25(-14.714,3.452) G27(-15.839,3.452) G29(-17.221,3.452) G31(-18.349,3.452) G33(-19.728,3.452) G35(-20.856,3.452) G37(-22.235,3.452) G39(-23.363,3.452) G41(-24.745,3.452) G43(-25.87,3.452) G45(-27.252,3.452) G47(-28.377,3.452) G49(-29.759,3.452) G51(-30.886,3.452) G53(-32.266,3.452) G55(-33.393,3.452) G57(-34.773,3.452) H22(-12.606,4.58) H23(-13.114,4.173) H57(-35.057,4.1) J22(-12.606,5.392) J23(-13.114,4.986) J58(-35.377,4.826) K9(-5.032,5.862) K10(-5.936,5.7) K12(-6.888,5.7) K14(-7.841,5.7) K16(-8.793,5.7) K18(-9.746,5.7) K19(-10.698,5.7) K21(-11.651,5.7) K23(-13.114,5.799) K57(-35.057,5.476) L10(-5.476,6.337) L11(-6.411,6.144) L13(-7.363,6.144) L15(-8.316,6.144) L17(-9.268,6.144) L18(-10.221,6.144) L20(-11.179,6.205) L22(-12.606,6.205) L58(-35.377,6.126) M9(-5.032,6.815) M20(-11.179,7.018) M21(-11.687,6.612) M22(-12.606,7.018) M23(-13.114,6.612) M57(-35.057,6.777) N10(-5.476,7.29) N21(-11.687,7.424) N23(-13.114,7.424) N58(-35.377,7.427) P9(-5.032,7.767) P20(-11.179,7.831) P22(-12.606,7.831) P57(-35.057,8.077) R10(-5.476,8.242) R20(-11.179,8.644) R21(-11.687,8.237) R22(-12.606,8.644) R23(-13.114,8.237) T9(-5.032,8.72) T21(-11.687,9.05) T23(-13.114,9.05) T58(-35.377,8.727) U9(-5.032,9.672) U10(-5.476,9.195) U20(-11.179,9.456) U22(-12.606,9.456) U57(-35.057,9.378) V10(-5.476,10.147) V21(-11.687,9.863) V23(-13.114,9.863) V58(-35.377,10.028) W9(-5.032,10.625) W20(-11.179,10.269) W21(-11.687,10.676) W22(-12.606,10.269) W23(-13.114,10.676) W57(-35.057,10.678) Y10(-5.476,11.1) Y20(-11.179,11.082) Y22(-12.606,11.082)
  round 0.305 smd: A8(-4.536,0) A9(-5.451,0) A11(-6.365,0) A12(-7.117,0) A14(-8.031,0) A15(-8.946,0) A17(-9.693,0) A18(-10.607,0) A20(-11.521,0) A21(-12.273,0) A23(-13.188,0) A24(-14.023,0.325) A25(-14.714,0) A27(-15.839,0) A28(-16.53,0.325) A29(-17.221,0) A31(-18.349,0) A32(-19.037,0.325) A33(-19.728,0) A35(-20.856,0) A36(-21.547,0.325) A37(-22.235,0) A39(-23.363,0) A40(-24.054,0.325) A41(-24.745,0) A43(-25.87,0) A44(-26.561,0.325) A45(-27.252,0) A47(-28.377,0) A48(-29.068,0.325) A49(-29.759,0) A51(-30.886,0) A52(-31.575,0.325) A53(-32.266,0) A55(-33.393,0) A56(-34.084,0.325) A57(-34.773,0) AA1(0,11.717) AA2(-0.65,11.717) AA3(-1.3,11.679) AA4(-1.951,11.679) AA59(-36.027,11.638) AA60(-36.678,11.638) AA61(-37.328,11.638) AA62(-37.978,11.676) AA63(-38.628,11.676) AB5(-2.637,12.052) AB6(-3.287,12.052) AB7(-3.937,12.052) AB8(-4.587,12.052) AC1(0,12.466) AC2(-0.65,12.466) AC3(-1.3,12.504) AC4(-1.951,12.504) AC59(-36.027,12.464) AC60(-36.678,12.464) AC61(-37.328,12.464) AC62(-37.978,12.426) AC63(-38.628,12.426) AD1(0,13.216) AD2(-0.65,13.216) AD3(-1.3,13.178) AD4(-1.951,13.178) AD5(-2.637,13.005) AD6(-3.287,13.005) AD7(-3.937,13.005) AD8(-4.587,13.005) AD59(-36.027,13.137) AD60(-36.678,13.137) AD61(-37.328,13.137) AD62(-37.978,13.175) AD63(-38.628,13.175) AE5(-2.637,13.957) AE6(-3.287,13.957) AE7(-3.937,13.957) AE8(-4.587,13.957) AE59(-36.027,13.962) AE60(-36.678,13.962) AE61(-37.328,13.962) AE62(-37.978,13.924) AE63(-38.628,13.924) AF1(0,13.965) AF2(-0.65,13.965) AF3(-1.3,14.003) AF4(-1.951,14.003) AG1(0,14.714) AG2(-0.65,14.714) AG3(-1.3,14.676) AG4(-1.951,14.676) AG5(-2.637,14.91) AG6(-3.287,14.91) AG7(-3.937,14.91) AG8(-4.587,14.91) AG21(-11.956,15.121) AG60(-36.352,14.602) AG61(-37.003,14.602) AG62(-37.653,14.602) AG63(-38.303,14.602) AH1(0,15.464) AH2(-0.65,15.464) AH3(-1.3,15.502) AH4(-1.951,15.502) AH10(-5.652,15.476) AH11(-6.464,15.476) AH13(-7.277,15.476) AH14(-8.09,15.476) AH16(-8.903,15.476) AH17(-9.716,15.476) AH19(-10.528,15.476) AH20(-11.341,15.476) AH60(-36.678,15.278) AH61(-37.328,15.278) AH62(-37.978,15.278) AH63(-38.628,15.278) AJ5(-2.637,15.862) AJ6(-3.287,15.862) AJ7(-3.937,15.862) AJ8(-4.587,15.862) AJ10(-5.652,16.126) AJ11(-6.464,16.126) AJ13(-7.277,16.126) AJ14(-8.09,16.126) AJ60(-36.352,15.954) AJ61(-37.003,15.954) AJ62(-37.653,15.954) AJ63(-38.303,15.954) AK1(0,16.213) AK2(-0.65,16.213) AK3(-1.3,16.175) AK4(-1.951,16.175) AK8(-4.303,16.452) AK18(-9.848,16.266) AK20(-10.8,16.266) AK21(-11.753,16.266) AK60(-36.678,16.523) AK61(-37.328,16.523) AK62(-37.978,16.629) AK63(-38.628,16.629) AL1(0,16.962) AL2(-0.65,16.962) AL3(-1.3,17) AL4(-1.951,17) AL5(-2.901,16.777) AL7(-3.739,16.777) AL8(-4.303,17.102) AL10(-5.657,16.777) AL11(-6.22,17.102) AL13(-7.577,16.777) AL15(-8.141,17.102) AL17(-9.223,16.584) AL18(-9.848,16.916) AL20(-10.8,16.916) AL21(-11.753,16.916) AL22(-12.705,16.916) AL23(-13.528,16.916) AL25(-14.503,16.916) AL26(-15.456,16.916) AL28(-16.408,16.916) AL29(-17.361,16.916) AL31(-18.26,16.591) AL32(-18.824,16.916) AL33(-19.726,16.916) AL35(-20.729,16.916) AL36(-21.58,16.916) AL38(-22.634,16.916) AL39(-23.541,16.591) AL40(-24.13,16.916) AL42(-24.943,16.916) AL43(-25.898,16.916) AL45(-26.873,16.916) AL46(-27.803,16.916) AL48(-28.854,16.916) AL49(-29.759,16.916) AL51(-30.759,16.916) AL52(-31.582,16.916) AL54(-32.609,16.916) AL55(-33.561,16.916) AL57(-34.508,16.916) AL58(-35.408,16.916) AL60(-36.352,17.17) AL61(-37.003,17.17) AM1(0,17.711) AM2(-0.65,17.711) AM3(-1.3,17.673) AM4(-1.951,17.673) AM5(-2.901,17.427) AM7(-3.739,17.427) AM8(-4.303,17.752) AM10(-5.657,17.427) AM11(-6.22,17.752) AM13(-7.577,17.427) AM15(-8.141,17.752) AM17(-9.223,17.234) AM18(-9.848,17.567) AM20(-10.8,17.567) AM21(-11.753,17.567) AM22(-12.705,17.567) AM23(-13.528,17.567) AM25(-14.503,17.567) AM26(-15.456,17.567) AM28(-16.408,17.567) AM29(-17.361,17.567) AM31(-18.26,17.242) AM32(-18.824,17.567) AM33(-19.726,17.567) AM35(-20.729,17.567) AM36(-21.58,17.567) AM38(-22.634,17.567) AM40(-24.13,17.567) AM42(-24.943,17.567) AM43(-25.898,17.567) AM45(-26.873,17.567) AM46(-27.803,17.567) AM48(-28.854,17.567) AM49(-29.759,17.567) AM51(-30.759,17.567) AM52(-31.582,17.567) AM54(-32.609,17.567) AM55(-33.561,17.567) AM57(-34.508,17.567) AM58(-35.408,17.567) AM60(-36.678,17.816) AM61(-37.328,17.816) AM62(-37.978,17.709) AM63(-38.628,17.709) AN1(0,18.461) AN2(-0.65,18.461) AN3(-1.3,18.499) AN4(-1.951,18.499) AN5(-2.901,18.077) AN7(-3.739,18.077) AN8(-4.303,18.402) AN10(-5.657,18.077) AN11(-6.22,18.402) AN13(-7.577,18.077) AN15(-8.141,18.402) AN17(-9.223,17.884) AN18(-9.848,18.217) AN20(-10.8,18.217) AN21(-11.753,18.217) AN22(-12.705,18.217) AN23(-13.528,18.217) AN25(-14.503,18.217) AN26(-15.456,18.217) AN28(-16.408,18.217) AN29(-17.361,18.217) AN31(-18.26,17.892) AN32(-18.824,18.217) AN33(-19.726,18.217) AN35(-20.729,18.217) AN36(-21.58,18.217) AN38(-22.634,18.217) AN39(-23.541,17.892) AN40(-24.13,18.217) AN42(-24.943,18.217) AN43(-25.898,18.217) AN45(-26.873,18.217) AN46(-27.803,18.217) AN48(-28.854,18.217) AN49(-29.759,18.217) AN51(-30.759,18.217) AN52(-31.582,18.217) AN54(-32.609,18.217) AN55(-33.561,18.217) AN57(-34.508,18.217) AN58(-35.408,18.217) AN60(-36.352,18.385) AN61(-37.003,18.385) AN62(-37.653,18.385) AN63(-38.303,18.385) AP1(0,19.21) AP2(-0.65,19.21) AP3(-1.3,19.172) AP4(-1.951,19.172) AP5(-2.901,18.727) AP7(-3.739,18.727) AP8(-4.303,19.053) AP10(-5.657,18.727) AP11(-6.22,19.053) AP13(-7.577,18.727) AP15(-8.141,19.053) AP17(-9.223,18.534) AP18(-9.848,18.867) AP20(-10.8,18.867) AP21(-11.753,18.867) AP22(-12.705,18.867) AP23(-13.528,18.867) AP25(-14.503,18.867) AP26(-15.456,18.867) AP28(-16.408,18.867) AP29(-17.361,18.867) AP31(-18.26,18.542) AP32(-18.824,18.867) AP33(-19.726,18.867) AP35(-20.729,18.867) AP36(-21.58,18.867) AP38(-22.634,18.867) AP39(-23.541,18.542) AP40(-24.13,18.867) AP42(-24.943,18.867) AP43(-25.898,18.867) AP45(-26.873,18.867) AP46(-27.803,18.867) AP48(-28.854,18.867) AP49(-29.759,18.867) AP51(-30.759,18.867) AP52(-31.582,18.867) AP54(-32.609,18.867) AP55(-33.561,18.867) AP57(-34.508,18.867) AP58(-35.408,18.867) AP60(-36.678,19.06) AP61(-37.328,19.06) AP62(-37.978,19.06) AP63(-38.628,19.06) AR5(-2.901,19.378) AR7(-3.739,19.378) AR8(-4.303,19.703) AR10(-5.657,19.378) AR11(-6.22,19.703) AR13(-7.577,19.378) AR15(-8.141,19.703) AR17(-9.223,19.185) AR18(-9.848,19.517) AR20(-10.8,19.517) AR21(-11.753,19.517) AR22(-12.705,19.517) AR23(-13.528,19.517) AR25(-14.503,19.517) AR26(-15.456,19.517) AR28(-16.408,19.517) AR29(-17.361,19.517) AR31(-18.26,19.192) AR32(-18.824,19.517) AR33(-19.726,19.517) AR35(-20.729,19.517) AR36(-21.58,19.517) AR38(-22.634,19.517) AR39(-23.541,19.192) AR40(-24.13,19.517) AR42(-24.943,19.517) AR43(-25.898,19.517) AR45(-26.873,19.517) AR46(-27.803,19.517) AR48(-28.854,19.517) AR49(-29.759,19.517) AR51(-30.759,19.517) AR52(-31.582,19.517) AR54(-32.609,19.517) AR55(-33.561,19.517) AR57(-34.508,19.517) AR58(-35.408,19.517) AT2(-0.65,19.959) AT3(-1.3,19.997) AT4(-1.951,19.997) AT5(-2.901,20.028) AT7(-3.739,20.028) AT10(-5.657,20.028) AT13(-7.577,20.028) AT35(-20.437,20.218) AT37(-22.012,20.218) AT40(-23.586,20.218) AT42(-25.161,20.218) AT43(-26.736,20.218) AT46(-28.311,20.218) AT49(-29.911,20.249) AT61(-37.003,19.634) AT62(-37.813,19.69) AU2(-0.655,20.648) AU3(-1.316,20.648) AU4(-1.976,20.648) AU6(-3.338,20.678) AU7(-4.163,20.678) AU8(-4.836,20.678) AU10(-5.662,20.678) AU11(-6.335,20.678) AU12(-7.16,20.678) AU14(-7.833,20.678) AU15(-8.659,20.678) AU16(-9.223,20.353) AU17(-9.86,20.678) AU18(-10.536,20.353) AU19(-11.105,20.678) AU20(-11.75,20.353) AU21(-12.398,20.678) AU22(-12.967,20.353) AU23(-13.642,20.678) AU24(-14.318,20.353) AU25(-14.994,20.678) AU26(-15.669,20.353) AU27(-16.238,20.678) AU28(-16.883,20.353) AU29(-17.531,20.678) AU30(-18.1,20.353) AU31(-18.776,20.678) AU33(-19.373,20.33) AU34(-19.975,20.678) AU35(-20.899,20.678) AU36(-21.549,20.678) AU37(-22.474,20.678) AU39(-23.124,20.678) AU40(-24.049,20.678) AU41(-24.699,20.678) AU42(-25.624,20.678) AU43(-26.274,20.678) AU44(-27.198,20.678) AU46(-27.849,20.678) AU47(-28.773,20.678) AU49(-29.423,20.678) AU50(-30.399,20.678) AU51(-30.98,20.353) AU52(-31.656,20.678) AU53(-32.332,20.353) AU54(-32.901,20.678) AU55(-33.546,20.353) AU56(-34.193,20.678) AU57(-34.762,20.353) AU58(-35.438,20.678) AU59(-36.002,20.353) AU60(-36.566,20.678) AU61(-37.277,20.401) AU62(-37.978,20.663) AV3(-1.321,21.308) AV4(-1.976,21.308) AV5(-2.664,21.328) AV6(-3.338,21.328) AV7(-4.163,21.328) AV8(-4.836,21.328) AV10(-5.662,21.328) AV11(-6.335,21.328) AV12(-7.16,21.328) AV14(-7.833,21.328) AV15(-8.659,21.328) AV16(-9.223,21.003) AV17(-9.86,21.328) AV18(-10.536,21.003) AV19(-11.105,21.328) AV20(-11.75,21.003) AV21(-12.398,21.328) AV22(-12.967,21.003) AV23(-13.642,21.328) AV24(-14.318,21.003) AV25(-14.994,21.328) AV26(-15.669,21.003) AV27(-16.238,21.328) AV28(-16.883,21.003) AV29(-17.531,21.328) AV30(-18.1,21.003) AV31(-18.776,21.328) AV33(-19.401,21.003) AV34(-20.023,21.328) AV35(-20.848,21.328) AV36(-21.598,21.328) AV37(-22.423,21.328) AV39(-23.172,21.328) AV40(-23.998,21.328) AV41(-24.747,21.328) AV42(-25.573,21.328) AV43(-26.322,21.328) AV44(-27.148,21.328) AV46(-27.897,21.328) AV47(-28.722,21.328) AV49(-29.472,21.328) AV50(-30.297,21.328) AV51(-30.98,21.003) AV52(-31.656,21.328) AV53(-32.332,21.003) AV54(-32.901,21.328) AV55(-33.546,21.003) AV56(-34.193,21.328) AV57(-34.762,21.003) AV58(-35.438,21.328) AV59(-36.002,21.003) AV60(-36.566,21.328) AV61(-37.302,21.052) AW4(-1.976,21.968) AW5(-2.626,21.979) AW6(-3.376,21.979) AW7(-4.125,21.979) AW8(-4.874,21.979) AW10(-5.624,21.979) AW11(-6.373,21.979) AW12(-7.122,21.979) AW14(-7.871,21.979) AW15(-8.621,21.979) AW16(-9.223,21.654) AW17(-9.86,21.979) AW18(-10.536,21.654) AW19(-11.212,21.979) AW21(-12.291,21.979) AW22(-12.967,21.654) AW23(-13.642,21.979) AW24(-14.318,21.654) AW25(-14.994,21.979) AW26(-15.669,21.654) AW27(-16.345,21.979) AW29(-17.424,21.979) AW30(-18.1,21.654) AW31(-18.776,21.979) AW33(-19.451,21.654) AW34(-20.023,21.979) AW35(-20.848,21.979) AW36(-21.598,21.979) AW37(-22.423,21.979) AW39(-23.172,21.979) AW40(-23.998,21.979) AW41(-24.747,21.979) AW42(-25.573,21.979) AW43(-26.322,21.979) AW44(-27.148,21.979) AW46(-27.897,21.979) AW47(-28.722,21.979) AW49(-29.472,21.979) AW50(-30.297,21.979) AW51(-30.98,21.654) AW52(-31.656,21.979) AW53(-32.332,21.654) AW54(-33.007,21.979) AW56(-34.087,21.979) AW57(-34.762,21.654) AW58(-35.438,21.979) AW59(-36.002,21.654) AW60(-36.566,21.979) AY6(-3.376,22.629) AY7(-4.125,22.629) AY8(-4.874,22.629) AY10(-5.624,22.629) AY11(-6.373,22.629) AY12(-7.122,22.629) AY14(-7.871,22.629) AY15(-8.621,22.629) AY16(-9.185,22.304) AY17(-9.86,22.629) AY18(-10.536,22.304) AY19(-11.212,22.629) AY21(-12.291,22.629) AY22(-12.967,22.304) AY23(-13.642,22.629) AY24(-14.318,22.304) AY25(-14.994,22.629) AY26(-15.669,22.304) AY27(-16.345,22.629) AY29(-17.424,22.629) AY30(-18.1,22.304) AY31(-18.776,22.629) AY33(-19.451,22.304) AY34(-20.023,22.629) AY35(-20.848,22.629) AY36(-21.598,22.629) AY37(-22.423,22.629) AY39(-23.172,22.629) AY40(-23.998,22.629) AY41(-24.747,22.629) AY42(-25.573,22.629) AY43(-26.322,22.629) AY44(-27.148,22.629) AY46(-27.897,22.629) AY47(-28.722,22.629) AY49(-29.472,22.629) AY50(-30.297,22.629) AY51(-30.98,22.304) AY52(-31.656,22.629) AY53(-32.332,22.304) AY54(-33.007,22.629) AY56(-34.087,22.629) AY57(-34.762,22.304) AY58(-35.438,22.629) B4(-1.92,0.65) B5(-3.139,0.643) B6(-4.12,0.643) B8(-4.892,0.643) B9(-5.715,0.643) B11(-6.695,0.643) B12(-7.468,0.643) B14(-8.296,0.643) B15(-9.276,0.643) B17(-10.048,0.643) B18(-10.871,0.643) B20(-11.852,0.643) B21(-12.273,1.196) B22(-12.624,0.643) B23(-13.452,0.643) B24(-14.023,0.975) B25(-14.714,0.65) B26(-15.278,0.975) B27(-15.839,0.65) B28(-16.53,0.975) B29(-17.221,0.65) B30(-17.785,0.975) B31(-18.349,0.65) B32(-19.037,0.975) B33(-19.728,0.65) B34(-20.292,0.975) B35(-20.856,0.65) B36(-21.547,0.975) B37(-22.235,0.65) B38(-22.799,0.975) B39(-23.363,0.65) B40(-24.054,0.975) B41(-24.745,0.65) B42(-25.306,0.975) B43(-25.87,0.65) B44(-26.561,0.975) B45(-27.252,0.65) B46(-27.816,0.975) B47(-28.377,0.65) B48(-29.068,0.975) B49(-29.759,0.65) B50(-30.323,0.975) B51(-30.886,0.65) B52(-31.575,0.975) B53(-32.266,0.65) B54(-32.83,0.975) B55(-33.393,0.65) B56(-34.084,0.975) B57(-34.773,0.65) B58(-35.336,0.975) B59(-35.9,0.65) B60(-36.665,0.66) C3(-1.303,1.303) C4(-2.118,1.273) C5(-2.774,1.196) C6(-3.774,1.196) C8(-4.536,1.196) C9(-5.349,1.196) C11(-6.355,1.196) C12(-7.117,1.196) C14(-7.93,1.196) C15(-8.931,1.196) C17(-9.693,1.196) C18(-10.505,1.196) C20(-11.511,1.196) C21(-11.892,1.786) C22(-12.68,1.786) C23(-13.086,1.196) C24(-14.051,2.032) C25(-14.714,1.3) C26(-15.278,1.626) C27(-15.839,1.3) C28(-16.558,2.032) C29(-17.221,1.3) C30(-17.785,1.626) C31(-18.349,1.3) C32(-19.065,2.032) C33(-19.728,1.3) C34(-20.292,1.626) C35(-20.856,1.3) C36(-21.572,2.032) C37(-22.235,1.3) C38(-22.799,1.626) C39(-23.363,1.3) C40(-24.082,2.032) C41(-24.745,1.3) C42(-25.306,1.626) C43(-25.87,1.3) C44(-26.589,2.032) C45(-27.252,1.3) C46(-27.816,1.626) C47(-28.377,1.3) C48(-29.07,2.032) C49(-29.759,1.3) C50(-30.323,1.626) C51(-30.886,1.3) C52(-31.577,1.991) C53(-32.266,1.3) C54(-32.83,1.626) C55(-33.393,1.3) C56(-34.084,1.991) C57(-34.773,1.3) C58(-35.336,1.626) C59(-35.9,1.3) C61(-37.003,1.237) D2(-0.65,2.075) D3(-1.3,2.037) D5(-2.677,1.841) D6(-3.368,1.786) D8(-4.155,1.786) D9(-4.943,1.786) D11(-5.852,1.786) D12(-6.736,1.786) D14(-7.523,1.786) D15(-8.43,1.786) D17(-9.312,1.786) D18(-10.099,1.786) D20(-11.008,1.786) D21(-12.235,2.423) D23(-13.376,1.786) D25(-14.714,1.951) D26(-15.278,2.276) D27(-15.839,1.951) D29(-17.221,1.951) D30(-17.785,2.276) D31(-18.349,1.951) D33(-19.728,1.951) D34(-20.292,2.276) D35(-20.856,1.951) D37(-22.235,1.951) D38(-22.799,2.276) D39(-23.363,1.951) D41(-24.745,1.951) D42(-25.306,2.276) D43(-25.87,1.951) D45(-27.252,1.951) D46(-27.816,2.276) D47(-28.377,1.951) D49(-29.759,1.951) D50(-30.323,2.276) D51(-30.886,1.951) D53(-32.266,1.951) D54(-32.83,2.276) D55(-33.393,1.951) D57(-34.773,1.951) D58(-35.336,2.276) D59(-35.9,1.951) D60(-36.678,1.801) D61(-37.328,1.801) D62(-37.978,2.035) E2(-0.65,2.725) E3(-1.3,2.687) E4(-1.951,2.687) E5(-2.601,2.619) E6(-3.553,2.619) E8(-4.506,2.619) E10(-5.458,2.619) E11(-6.411,2.619) E13(-7.363,2.619) E15(-8.316,2.619) E17(-9.268,2.619) E18(-10.221,2.619) E20(-11.173,2.619) E59(-36.027,2.647) E60(-36.678,2.647) E61(-37.328,2.647) E62(-37.978,2.685) F2(-0.65,3.475) F3(-1.3,3.513) F4(-1.951,3.513) F5(-2.601,3.269) F6(-3.553,3.269) F8(-4.506,3.269) F10(-5.458,3.269) F11(-6.411,3.269) F13(-7.363,3.269) F15(-8.316,3.269) F17(-9.268,3.269) F18(-10.221,3.269) F20(-11.173,3.269) F59(-36.027,3.472) F60(-36.678,3.472) F61(-37.328,3.472) F62(-37.978,3.434) F63(-38.628,3.434) G1(0,4.224) G2(-0.65,4.224) G3(-1.3,4.186) G4(-1.951,4.186) G5(-2.601,3.919) G6(-3.553,3.919) G8(-4.506,3.919) G10(-5.458,3.919) G11(-6.411,3.919) G13(-7.363,3.919) G15(-8.316,3.919) G17(-9.268,3.919) G18(-10.221,3.919) G20(-11.173,3.919) H5(-2.601,4.569) H6(-3.553,4.569) H8(-4.506,4.569) H10(-5.458,4.569) H11(-6.411,4.569) H13(-7.363,4.569) H15(-8.316,4.569) H17(-9.268,4.569) H18(-10.221,4.569) H20(-11.173,4.569) H59(-36.027,4.145) H60(-36.678,4.145) H61(-37.328,4.145) H62(-37.978,4.183) H63(-38.628,4.183) J1(0,4.973) J2(-0.65,4.973) J3(-1.3,5.011) J4(-1.951,5.011) J5(-2.626,5.22) J6(-3.566,5.22) J8(-4.506,5.22) J10(-5.458,5.22) J11(-6.411,5.22) J13(-7.363,5.22) J15(-8.316,5.22) J17(-9.268,5.22) J18(-10.221,5.22) J20(-11.173,5.22) J21(-12.095,4.986) J59(-36.027,4.971) J60(-36.678,4.971) J61(-37.328,4.971) J62(-37.978,4.933) J63(-38.628,4.933) K1(0,5.723) K2(-0.65,5.723) K3(-1.3,5.685) K4(-1.951,5.685) K59(-36.027,5.644) K60(-36.678,5.644) K61(-37.328,5.644) K62(-37.978,5.682) K63(-38.628,5.682) L1(0,6.472) L2(-0.65,6.472) L3(-1.3,6.51) L4(-1.951,6.51) L5(-2.637,6.337) L6(-3.287,6.337) L7(-3.937,6.337) L8(-4.587,6.337) L59(-36.027,6.469) L60(-36.678,6.469) L61(-37.328,6.469) L62(-37.978,6.431) L63(-38.628,6.431) N1(0,7.221) N2(-0.65,7.221) N3(-1.3,7.183) N4(-1.951,7.183) N5(-2.637,7.29) N6(-3.287,7.29) N7(-3.937,7.29) N8(-4.587,7.29) N59(-36.027,7.142) N60(-36.678,7.142) N61(-37.328,7.142) N62(-37.978,7.181) N63(-38.628,7.181) P1(0,7.971) P2(-0.65,7.971) P3(-1.3,8.009) P4(-1.951,8.009) P59(-36.027,7.968) P60(-36.678,7.968) P61(-37.328,7.968) P62(-37.978,7.93) P63(-38.628,7.93) R5(-2.637,8.242) R6(-3.287,8.242) R7(-3.937,8.242) R8(-4.587,8.242) T1(0,8.72) T2(-0.65,8.72) T3(-1.3,8.682) T4(-1.951,8.682) T59(-36.027,8.641) T60(-36.678,8.641) T61(-37.328,8.641) T62(-37.978,8.679) T63(-38.628,8.679) U1(0,9.469) U2(-0.65,9.469) U3(-1.3,9.507) U4(-1.951,9.507) U5(-2.637,9.195) U6(-3.287,9.195) U7(-3.937,9.195) U8(-4.587,9.195) U59(-36.027,9.467) U60(-36.678,9.467) U61(-37.328,9.467) U62(-37.978,9.428) U63(-38.628,9.428) V1(0,10.218) V2(-0.65,10.218) V3(-1.3,10.18) V4(-1.951,10.18) V5(-2.637,10.147) V6(-3.287,10.147) V7(-3.937,10.147) V8(-4.587,10.147) V59(-36.027,10.14) V60(-36.678,10.14) V61(-37.328,10.14) V62(-37.978,10.178) V63(-38.628,10.178) Y1(0,10.968) Y2(-0.65,10.968) Y3(-1.3,11.006) Y4(-1.951,11.006) Y5(-2.637,11.1) Y6(-3.287,11.1) Y7(-3.937,11.1) Y8(-4.587,11.1) Y59(-36.027,10.965) Y60(-36.678,10.965) Y61(-37.328,10.965) Y62(-37.978,10.927) Y63(-38.628,10.927)
  round 0.33 smd: AK22(-12.654,16.266) AK23(-13.528,16.266) AK25(-14.503,16.266) AK26(-15.456,16.266) AK28(-16.408,16.266) AK29(-17.31,16.266) AK32(-18.824,16.266) AK33(-19.726,16.266) AK35(-20.729,16.266) AK36(-21.58,16.266) AK38(-22.609,16.266) AK40(-24.105,16.266) AK42(-24.943,16.266) AK43(-25.898,16.266) AK45(-26.873,16.266) AK46(-27.777,16.266) AK48(-28.829,16.266) AK49(-29.733,16.266) AK51(-30.734,16.266) AK52(-31.582,16.266) AK54(-32.609,16.266) AK55(-33.561,16.266) AK57(-34.508,16.266) AK58(-35.408,16.266)
SHORTPADS
  custom 0.19x0.19 smd: 1(-0.483,0) 2(0.483,0)
SI1553CDL-T1-GE3_SC70-6
  oval 0.406x0.66 smd: 1(0,0) 2(0.65,0) 3(1.3,0) 4(1.3,1.791) 5(0.65,1.791) 6(0,1.791)
SI4835DDY-T1-E3_SO8
  oval 0.635x1.727 smd: 1(0,0) 2(1.27,0) 3(2.54,0) 4(3.81,0) 5(3.81,5.285) 6(2.54,5.285) 7(1.27,5.285) 8(0,5.285)
SI7716ADN-T1-GE3_POWERPAK8-5
  oval 0.406x0.991 smd: 1(0,0) 2(0.66,0) 3(1.32,0) 4(1.98,0)
  custom 0.559x0.559 smd: 5(0.99,2.247)
SINGA_2SJ3095-022111F_6P-T
  oval 0.991x1.803 hole 0.61x1.397: 1(0,0) 2(-9.5,5.5) 3(0,5.2) 4(0,7.8) 5(-9.5,0) 6(-9.5,2.75) 7(0,2.65)
SIR472DP-T1-GE3_POWERPAK8-5
  oval 0.61x1.27 smd: 1(0,0) 2(1.27,0) 3(2.54,0) 4(3.81,0)
  custom 1.105x1.105 smd: 5(1.905,3.36)
SIS412DN-T1-GE3_POWERPAK8-5
  oval 0.406x0.991 smd: 1(0,0) 2(0.66,0) 3(1.32,0) 4(1.98,0)
  custom 0.559x0.559 smd: 5(0.99,2.247)
SN74AUP1G04DCKR_SC70-5
  oval 0.406x0.889 smd: 1(0,0) 2(0.65,0) 3(1.3,0) 4(1.3,2.2) 5(0,2.2)
SN74CBT3257CPWR_TSSOP16
  oval 0.381x1.651 smd: 1(0,0) 2(0.65,0) 3(1.3,0) 4(1.95,0) 5(2.6,0) 6(3.25,0) 7(3.9,0) 8(4.55,0) 9(4.55,5.775) 10(3.9,5.775) 11(3.25,5.775) 12(2.6,5.775) 13(1.95,5.775) 14(1.3,5.775) 15(0.65,5.775) 16(0,5.775)
SSM3K7002FU_SC70-3
  oval 0.508x0.991 smd: 1(0,0) 2(0.65,1.9) 3(-0.65,1.9)
SW_NTC311-EA1T-A160T_4P
  rect 1.651x1.041 smd: 1(0,0) 2(3.85,0)
  rect 1.651x1.041 hole 0.66: 3(-0.1,-1.525) 4(3.95,-1.525)
SW_SKRBAAE010_4P
  rect 0.889x1.219 smd: 1(0,0) 2(3.9,0) 3(0,4.075) 4(3.9,4.075)
SW_SSAL120100_3P
  rect 0.787x0.787 smd: 1(0,0) 3(3.4,0)
  rect 1.194x0.787 smd: 2(1.7,0)
  rect 1.041x0.889 smd: 4(-2.375,-1.6) 5(5.775,-1.6)
SY8206DQNC_QFN10_3X3
  oval 0.254x0.61 smd: 1(0,0) 2(0.45,0) 3(0.9,0) 4(1.35,0) 5(1.8,0) 6(2.25,0)
  rect 1.168x0.254 smd: 7(2.19,-0.675)
  rect 0.914x2.007 smd: 8(2.065,-2)
  custom 0.483x0.483 smd: 9(1.077,-1.775)
  rect 0.813x1.168 smd: 10(0.137,-1.587)
TAI-T_HCB1608KF-121T3_L0603_2P
  rect 0.991x0.787 smd: 1(0,0) 2(1.6,0)
TAI-T_HCB2012KF-121T50_2P
  rect 0.991x0.991 smd: 1(0,0) 2(2,0)
TC7SH08FU_SSOP5
  oval 0.406x0.787 smd: 1(0,0) 2(0.65,0) 3(1.3,0) 4(1.3,1.9) 5(0,1.9)
TE_C-PT13-061_20P-T
  oval 0.838x0.66 hole 0.533: 1(0,0) 2(0,3.4) 7(1.8,0) 8(1.8,3.4) 13(3.6,0) 14(3.6,3.4) 19(5.4,0) 20(5.4,3.4)
  oval 0.66x0.838 hole 0.533: 3(0.45,0.8) 4(0.45,4.2) 5(1.35,0.8) 6(1.35,4.2) 9(2.25,0.8) 10(2.25,4.2) 11(3.15,0.8) 12(3.15,4.2) 15(4.05,0.8) 16(4.05,4.2) 17(4.95,0.8) 18(4.95,4.2)
  oval 1.194x2.845 hole 0.711x2.311: 21(8.31,1.275) 22(-2.89,1.275)
  oval 1.194x1.905 hole 0.711x1.397: 23(-2.77,-8.525) 24(7.97,-8.525)
TE_C-PT13-067_9P-T
  round 1.194 hole 0.787: 1(0,0) 2(-2.5,0) 3(-4.5,0) 4(-7,0) 5(-7.5,-1.5) 6(-5.5,-1.5) 7(-3.5,-1.5) 8(-1.5,-1.5) 9(0.5,-1.5)
  oval 1.549x2.667 hole 0.787x1.905: 10(2.92,0.39) 11(-9.88,0.39)
  oval 1.549x2.057 hole 0.787x1.295: 12(4.36,-9.9) 13(-11.34,-9.9)
TLV62150RGTR_QFN16_3X3
  oval 0.254x1.016 smd: 1(0,0) 2(0.5,0) 3(1,0) 4(1.5,0) 9(1.5,2.975) 10(1,2.975) 11(0.5,2.975) 12(0,2.975)
  oval 1.016x0.254 smd: 5(2.238,0.738) 6(2.238,1.238) 7(2.238,1.738) 8(2.238,2.238) 13(-0.738,2.238) 14(-0.738,1.738) 15(-0.738,1.238) 16(-0.738,0.738)
  rect 1.702x1.702 smd: 17(0.75,1.488)
TOKO_1239AS-H-2R2N-P2_2P
  rect 0.787x2.007 smd: 1(0,0) 2(2,0)
TPC12
  round 0.305 smd: 1(0,0)
TPS22966DPUR_SON14_2X3
  oval 0.203x0.762 smd: 1(0,0) 2(0.4,0) 3(0.8,0) 4(1.2,0) 5(1.6,0) 6(2,0) 7(2.4,0) 8(2.4,2.05) 9(2,2.05) 10(1.6,2.05) 11(1.2,2.05) 12(0.8,2.05) 13(0.4,2.05) 14(0,2.05)
  rect 2.489x0.889 smd: 15(1.2,1.025)
TPS51285BRUKR_QFN20_3X3
  oval 0.203x1.016 smd: 1(0,0) 2(0.4,0) 3(0.8,0) 4(1.2,0) 5(1.6,0) 11(1.6,2.975) 12(1.2,2.975) 13(0.8,2.975) 14(0.4,2.975) 15(0,2.975)
  oval 1.016x0.203 smd: 6(2.288,0.688) 7(2.288,1.088) 8(2.288,1.488) 9(2.288,1.888) 10(2.288,2.288) 16(-0.688,2.288) 17(-0.688,1.888) 18(-0.688,1.488) 19(-0.688,1.088) 20(-0.688,0.688)
  rect 1.702x1.702 smd: 21(0.8,1.488)
TPS51624RSM_QFN32_4X4
  oval 0.203x0.889 smd: 1(0,0) 2(0.4,0) 3(0.8,0) 4(1.2,0) 5(1.6,0) 6(2,0) 7(2.4,0) 8(2.8,0) 17(2.8,4.1) 18(2.4,4.1) 19(2,4.1) 20(1.6,4.1) 21(1.2,4.1) 22(0.8,4.1) 23(0.4,4.1) 24(0,4.1)
  oval 0.889x0.203 smd: 9(3.45,0.65) 10(3.45,1.05) 11(3.45,1.45) 12(3.45,1.85) 13(3.45,2.25) 14(3.45,2.65) 15(3.45,3.05) 16(3.45,3.45) 25(-0.65,3.45) 26(-0.65,3.05) 27(-0.65,2.65) 28(-0.65,2.25) 29(-0.65,1.85) 30(-0.65,1.45) 31(-0.65,1.05) 32(-0.65,0.65)
  rect 2.794x2.794 smd: 33(1.4,2.05)
TVNST52302AB0_SOT523-3
  oval 0.508x0.559 smd: 1(0,0) 2(-0.5,-1.4) 3(0.5,-1.4)
TVWDF1004AD0_DFN9
  oval 0.203x0.686 smd: 1(0,0) 2(0.5,0) 4(1.5,0) 5(2,0) 6(2,0.875) 7(1.5,0.875) 8(0.5,0.875) 9(0,0.875)
  oval 0.406x1.549 smd: 3(1,0.437)
TXB0104PWR_TSSOP14
  oval 0.381x1.651 smd: 1(0,0) 2(0.65,0) 3(1.3,0) 4(1.95,0) 5(2.6,0) 6(3.25,0) 7(3.9,0) 8(3.9,5.775) 9(3.25,5.775) 10(2.6,5.775) 11(1.95,5.775) 12(1.3,5.775) 13(0.65,5.775) 14(0,5.775)
W25Q32FVSSIQ_SO8
  oval 0.635x1.676 smd: 1(0,0) 2(1.27,0) 3(2.54,0) 4(3.81,0) 5(3.81,7.25) 6(2.54,7.25) 7(1.27,7.25) 8(0,7.25)
W25Q64FVSSIQ_SO8
  oval 0.635x1.676 smd: 1(0,0) 2(1.27,0) 3(2.54,0) 4(3.81,0) 5(3.81,7.25) 6(2.54,7.25) 7(1.27,7.25) 8(0,7.25)
Y_CM31532768DZFT_2P
  rect 1.092x1.905 smd: 1(0,0) 2(2.5,0)
Y_Q13FC135000040_2P
  rect 0.991x1.803 smd: 1(0,0) 2(2.5,0)
Y_X3G024000DC1H_4P
  rect 1.397x1.194 smd: 1(0,0) 2(2.2,0) 3(2.2,1.7) 4(0,1.7)

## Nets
1.2V_DDR_PWROK: PR604.2 PU600.10
1.05V_M_PWRGD: PR512.1 RH135.2
1.05VA_PG: PR506.2 PR512.2 PU500.2
1.5VS_PWROK: PR404.1 PU400.4
1.05VS_VCCST_PG: R1132.2 R1180.2 U672.4 UCPU1.B59
1.8VS_PWROK: PR409.1 PU401.4
1.35V_B+: PC600.1 PC601.1 PC602.1 PC603.1 PL600.2 PQ600.5 PR606.1
3.3V_MSATA_EN: RH423.1 RH431.2 U682.2 UCPU1.N6
3.3V_TS_EN: R1162.1 U718.5 UCPU1.N7
3/5V_B+: PC303.1 PC313.1 PC314.1 PC315.1 PL300.2 PL303.2 PQ300.1 PQ301.1 PR445.1 PR457.1 PU300.12
3V/5VALW_EN: PC312.1 PR314.2 PR315.2 PU300.6
+0.675VS: CD101.1 CD129.1 CD132.1 CD133.1 CD135.1 CD136.1 CD139.1 CD140.1 CD142.1 CD143.1 CD144.1 PJP602.2 RD25.2 RD26.2 RD27.2 RD33.2 RD35.2 RD36.2 RD37.2 RD38.2 RD45.2 RD46.2 RD47.2 RD48.2 RD49.2 RD50.2 RD57.2 RD58.2 RD59.2 RD60.2 RD61.2 RD62.2 RD63.2 RD64.2 RD65.2 RD66.2 RD67.2 RD68.2 RD69.2 RD70.2 RD71.2 RD72.2 RD73.2 RD74.2 RD75.2 RD76.2 RD77.2 RD78.2 RD79.2 RD80.2 RD81.2 RD82.2 RD83.2 RD84.2 RD85.2 RD86.2 RD87.2 RD88.2 RD89.2 RD90.2 RD91.2 RD93.2 RD94.2 RD96.2 RD97.2 RD98.2 RD99.2 RD100.2
+0.675VSP: PC605.1 PC606.1 PJP602.1 PU600.2 PU600.20
+1.5V_B+: PC401.1 PC404.1 PC405.1 PL400.2 PU400.10 PU400.11 PU400.12
